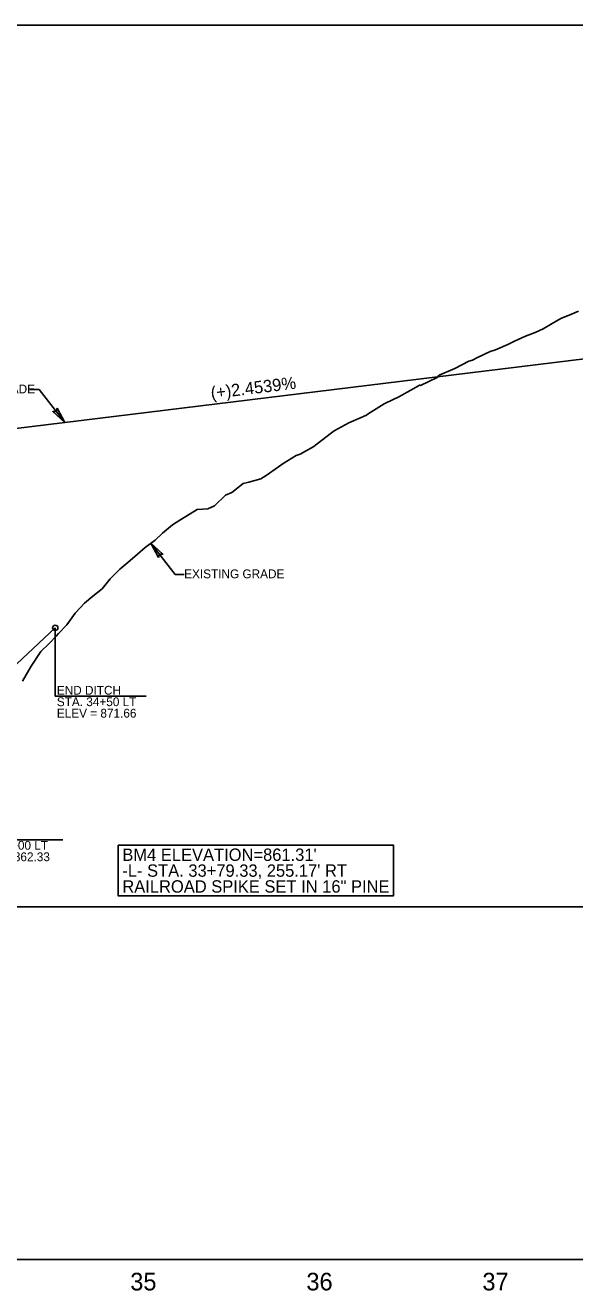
# Model space of a CAD drawing. Extents: x 1968019 to 1983409, y 545058 to 567558.
# Drawn here: x 1971276 to 1971588, y 566291 to 567008 of the extents above; entities that cross this region are included whole.
import ezdxf

# ---------------------------------------------------------------- set-up
doc = ezdxf.new("R2010")
doc.units = 0
for name, color, linetype in [('Exist Profile Cell', 7, 'Continuous'), ('Exist Vertical Profile Ground Line', 7, 'Continuous'), ('Exist Vertical Profile Horizontal Axis Label Major', 7, 'Continuous'), ('Old_Level_20', 7, 'Continuous'), ('Prop Grid Mask', 7, 'Continuous'), ('Prop Terminator CELL', 7, 'Continuous'), ('Prop Vertical Profile Ditch Grade Left', 7, 'Continuous'), ('Prop Vertical Profile Ditch Grade Left Label', 7, 'Continuous'), ('Prop Vertical Profile Grade', 7, 'Continuous'), ('Prop Vertical Profile Grade Label', 7, 'Continuous'), ('Prop VPI Label', 7, 'Continuous'), ('Scratch_Level_8', 7, 'Continuous')]:
    doc.layers.add(name, color=color, linetype=linetype)

msp = doc.modelspace()

# ---------------------------------------------------------------- linework, layer by layer
at = {"layer": 'Exist Profile Cell'}
msp.add_line((1968842.96, 566308.43), (1972642.96, 566308.43), dxfattribs=at)
at = {"layer": 'Exist Vertical Profile Ground Line'}
msp.add_lwpolyline([(1971274.29, 566636.39), (1971279.33, 566645.04), (1971284.8, 566653.24), (1971289.55, 566657.82), (1971293.38, 566661.94), (1971294.8, 566663.47), (1971299.55, 566668.38), (1971304.27, 566675.01), (1971309.55, 566680.76), (1971314.23, 566684.66), (1971319.55, 566688.74), (1971324.17, 566694.49), (1971329.55, 566699.92), (1971334.08, 566703.74), (1971339.55, 566708.5), (1971343.97, 566712.18), (1971349.55, 566716.49), (1971353.84, 566720.41), (1971359.55, 566725.21), (1971363.68, 566727.76), (1971369.55, 566731.3), (1971373.5, 566733.74), (1971379.56, 566734.18), (1971383.29, 566735.94), (1971389.56, 566741.97), (1971393.06, 566743.49), (1971399.56, 566748.52), (1971402.81, 566749.31), (1971409.57, 566751.27), (1971412.54, 566753.18), (1971419.57, 566758.1), (1971422.24, 566759.9), (1971429.58, 566764.36), (1971431.92, 566765.24), (1971439.59, 566769.47), (1971441.58, 566771.05), (1971449.59, 566777.28), (1971451.22, 566778.44), (1971459.6, 566782.98), (1971460.84, 566783.61), (1971469.61, 566787.38), (1971470.44, 566788.11), (1971479.62, 566793.82), (1971480.01, 566793.96), (1971488.17, 566797.94), (1971489.57, 566798.62), (1971489.63, 566798.66), (1971499.1, 566803.93), (1971499.65, 566804.34), (1971500.25, 566804.23), (1971509.66, 566808.67), (1971510.83, 566810.07), (1971519.68, 566813.86), (1971527.58, 566817.99), (1971529.69, 566818.52), (1971532.08, 566819.85), (1971539.71, 566823.34), (1971542.75, 566824.42), (1971549.73, 566827.48), (1971553.45, 566829.21), (1971559.76, 566832.12), (1971565.27, 566834.23), (1971569.78, 566836.35), (1971574.96, 566839.25), (1971579.8, 566842.21), (1971585.76, 566844.56), (1971589.83, 566846.27)], dxfattribs=at)
at = {"layer": 'Old_Level_20'}
for p, q in [((1971278.61, 566801.95), (1971283.77, 566801.95)), ((1971283.77, 566801.95), (1971298.37, 566783.2)), ((1971360.99, 566697.01), (1971347.2, 566714.68)), ((1971360.99, 566697.01), (1971366.16, 566697.01))]:
    msp.add_line(p, q, dxfattribs=at)
at = {"layer": 'Prop Grid Mask'}
msp.add_lwpolyline([(1971328.58, 566543.42), (1971484.91, 566543.42), (1971484.91, 566514.78), (1971328.58, 566514.78)], close=True, dxfattribs=at)
at = {"layer": 'Prop Terminator CELL'}
for points in [[(1971294.07, 566791.26), (1971298.37, 566783.2), (1971291.55, 566789.36), (1971293.52, 566789.44)], [(1971351.52, 566706.63), (1971347.2, 566714.68), (1971354.03, 566708.53), (1971352.06, 566708.45)]]:
    msp.add_lwpolyline(points, close=True, dxfattribs=at)
at = {"layer": 'Prop Vertical Profile Ditch Grade Left'}
msp.add_lwpolyline([(1971183.96, 566578.43), (1971242.96, 566620.08), (1971292.96, 566666.73)], dxfattribs=at)
at = {"layer": 'Prop Vertical Profile Ditch Grade Left Label'}
for p, q in [((1971292.96, 566666.73), (1971292.96, 566627.88)), ((1971344.56, 566627.88), (1971292.96, 566627.88)), ((1971297.23, 566546.45), (1971242.96, 566546.45))]:
    msp.add_line(p, q, dxfattribs=at)
msp.add_circle((1971292.96, 566666.73), 1.5, dxfattribs=at)
at = {"layer": 'Prop Vertical Profile Grade'}
msp.add_line((1970942.96, 566739.6), (1971612.96, 566821.8), dxfattribs=at)
at = {"layer": 'Scratch_Level_8'}
msp.add_lwpolyline([(1970942.96, 566508.43), (1972342.96, 566508.43), (1972342.96, 567008.43), (1970942.96, 567008.43)], close=True, dxfattribs=at)

# ---------------------------------------------------------------- texts
at = {"layer": 'Exist Vertical Profile Horizontal Axis Label Major'}
for s, p in [('35', (1971335.5, 566290.93)), ('36', (1971435.44, 566290.93)), ('37', (1971535.3, 566290.93))]:
    msp.add_text(s, height=10, dxfattribs=at).set_placement(p)
at = {"layer": 'Old_Level_20'}
for s, p in [('PROPOSED GRADE', (1971217.93, 566799.67)), ('EXISTING GRADE', (1971366.1, 566694.83))]:
    msp.add_text(s, height=5, rotation=360, dxfattribs=at).set_placement(p)
at = {"layer": 'Prop Vertical Profile Ditch Grade Left Label'}
for s, p in [('END DITCH', (1971293.84, 566628.8)), ('STA. 34+50 LT', (1971293.84, 566622.3)), ('ELEV = 871.66', (1971293.84, 566615.8)), ('STA. 34+00 LT', (1971243.7, 566540.87)), ('= 862.33', (1971263.7, 566534.37))]:
    msp.add_text(s, height=5, dxfattribs=at).set_placement(p)
at = {"layer": 'Prop Vertical Profile Grade Label'}
msp.add_text('(+)2.4539%', height=7, rotation=6.99498, dxfattribs=at).set_placement((1971381.59, 566796.44))
at = {"layer": 'Prop VPI Label'}
for s, p in [("BM4 ELEVATION=861.31'", (1971331.01, 566534.55)), ("-L- STA. 33+79.33, 255.17' RT", (1971331.01, 566525.55)), ('RAILROAD SPIKE SET IN 16" PINE', (1971331.01, 566516.55))]:
    msp.add_text(s, height=7, dxfattribs=at).set_placement(p)

doc.saveas('drawing.dxf')
